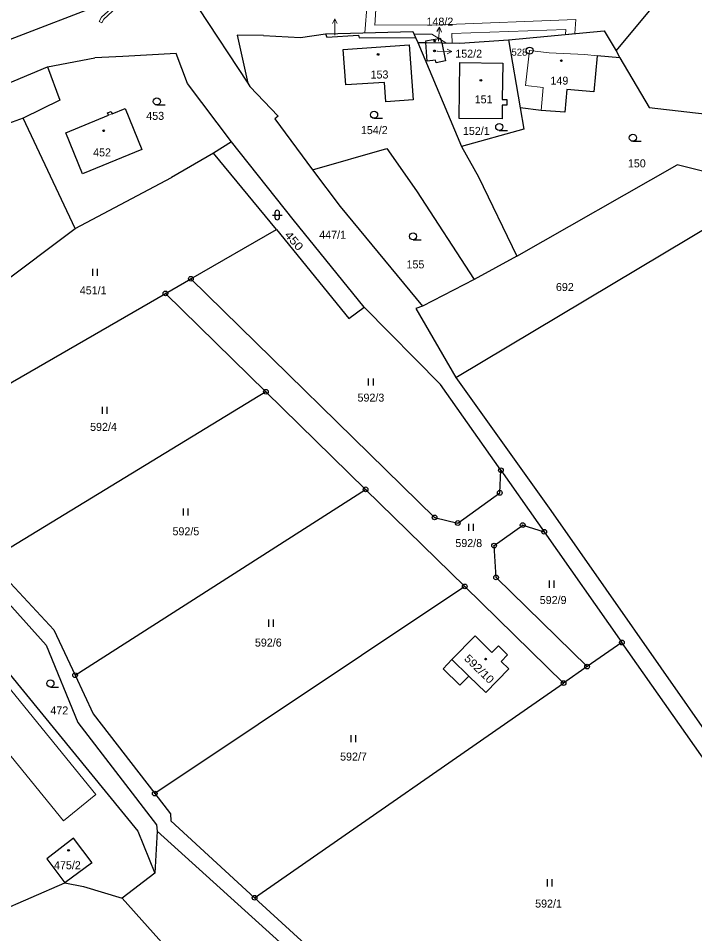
# Model space of a CAD drawing. Extents: x -727701 to -724405, y -960481 to -957284.
# Drawn here: x -726671.5 to -726527.9, y -958402.3 to -958207.9 of the extents above; entities that cross this region are included whole.
import ezdxf
from ezdxf.enums import TextEntityAlignment as Align

# ---------------------------------------------------------------- set-up
doc = ezdxf.new("R2010")
doc.units = 0
doc.header["$LTSCALE"] = 0.68
for name, color, linetype, lineweight in [('1', 7, 'Continuous', 25), ('13', 7, 'Continuous', 13), ('3', 7, 'Continuous', 25), ('4', 7, 'Continuous', 13), ('5', 7, 'Continuous', 25), ('7', 7, 'Continuous', 13), ('8', 7, 'Continuous', 25)]:
    doc.layers.add(name, color=color, linetype=linetype, lineweight=lineweight)
doc.layers.add('2', color=7, linetype='Continuous')

msp = doc.modelspace()

# ---------------------------------------------------------------- linework, layer by layer
at = {"layer": '1'}
for p, q in [((-726698.6, -958222.18), (-726650.53, -958203.52)), ((-726544.56, -958214.79), (-726535.63, -958204.12)), ((-726633.29, -958205.71), (-726622.75, -958221.7)), ((-726606.3, -958211.2), (-726587.7, -958210.7)), ((-726587.7, -958210.7), (-726587.17, -958211.95)), ((-726567.38, -958212.48), (-726547.13, -958210.56)), ((-726547.13, -958210.56), (-726544.56, -958214.79)), ((-726619.45, -958211.55), (-726625, -958211.5)), ((-726625, -958211.5), (-726622.75, -958221.7)), ((-726619.45, -958211.55), (-726611.6, -958211.95)), ((-726611.6, -958211.95), (-726606.3, -958211.2)), ((-726606.3, -958211.2), (-726606.01, -958211.92)), ((-726606.01, -958211.92), (-726599.29, -958211.45)), ((-726599.29, -958211.45), (-726599.13, -958212.08)), ((-726599.13, -958212.08), (-726587.17, -958211.95)), ((-726587.17, -958211.95), (-726586.7, -958213.05)), ((-726581.77, -958212.22), (-726585.02, -958212.76)), ((-726585.02, -958212.76), (-726584.99, -958213.07)), ((-726581.58, -958213.12), (-726581.77, -958212.22)), ((-726567.38, -958212.48), (-726564.95, -958226.93)), ((-726602.5, -958214.5), (-726588.5, -958213.5)), ((-726601.96, -958222.05), (-726602.5, -958214.5)), ((-726588.5, -958213.5), (-726587.66, -958225.23)), ((-726586.7, -958213.05), (-726584.99, -958213.07)), ((-726586.7, -958213.05), (-726577.38, -958235.15)), ((-726584.65, -958217), (-726584.99, -958213.07)), ((-726584.99, -958213.07), (-726581.58, -958213.12)), ((-726581.58, -958213.12), (-726580.81, -958216.9)), ((-726544.56, -958214.79), (-726543.75, -958216.31)), ((-726665.3, -958218.22), (-726655.26, -958216.27)), ((-726649.33, -958216.03), (-726655.26, -958216.27)), ((-726638.02, -958215.37), (-726649.33, -958216.03)), ((-726635.61, -958221.73), (-726638.02, -958215.37)), ((-726548.59, -958215.86), (-726549.31, -958223.52)), ((-726543.75, -958216.31), (-726548.59, -958215.86)), ((-726543.75, -958216.31), (-726537.55, -958226.85)), ((-726682.22, -958225.29), (-726665.3, -958218.22)), ((-726665.3, -958218.22), (-726662.67, -958225.3)), ((-726582.89, -958216.81), (-726584.65, -958217)), ((-726582.78, -958217.33), (-726582.89, -958216.81)), ((-726580.81, -958216.9), (-726582.78, -958217.33)), ((-726577.77, -958217.31), (-726568.63, -958217.42)), ((-726568.63, -958217.42), (-726568.73, -958225.13)), ((-726626.23, -958234.1), (-726635.61, -958221.73)), ((-726622.75, -958221.7), (-726622.35, -958222.4)), ((-726622.35, -958222.4), (-726616.35, -958228.71)), ((-726593.75, -958221.5), (-726601.96, -958222.05)), ((-726593.45, -958225.65), (-726593.75, -958221.5)), ((-726554.99, -958222.99), (-726555.44, -958227.83)), ((-726549.31, -958223.52), (-726554.99, -958222.99)), ((-726662.67, -958225.3), (-726670.49, -958229.12)), ((-726587.66, -958225.23), (-726593.45, -958225.65)), ((-726568.74, -958226.33), (-726568.78, -958229.28)), ((-726567.8, -958226.34), (-726568.74, -958226.33)), ((-726568.73, -958225.13), (-726567.78, -958225.15)), ((-726567.78, -958225.15), (-726567.8, -958226.34)), ((-726652.59, -958228), (-726651.78, -958227.67)), ((-726652.39, -958228.5), (-726652.59, -958228)), ((-726651.78, -958227.67), (-726651.58, -958228.17)), ((-726651.58, -958228.17), (-726648.85, -958227.05)), ((-726648.85, -958227.05), (-726645.28, -958235.78)), ((-726564.95, -958226.93), (-726564.19, -958231.42)), ((-726560.5, -958227.45), (-726564.95, -958226.93)), ((-726555.44, -958227.83), (-726560.5, -958227.45)), ((-726537.55, -958226.85), (-726496.15, -958231.66)), ((-726670.49, -958229.12), (-726679.19, -958232.29)), ((-726659.41, -958252.56), (-726670.49, -958229.12)), ((-726661.44, -958232.2), (-726652.39, -958228.5)), ((-726616.35, -958228.71), (-726617.06, -958229.24)), ((-726617.06, -958229.24), (-726609.02, -958240.05)), ((-726657.87, -958240.93), (-726661.44, -958232.2)), ((-726564.19, -958231.42), (-726577.38, -958235.15)), ((-726626.23, -958234.1), (-726630.03, -958236.53)), ((-726613.14, -958250.6), (-726626.23, -958234.1)), ((-726645.28, -958235.78), (-726657.87, -958240.93)), ((-726609.02, -958240.05), (-726593.25, -958235.58)), ((-726593.25, -958235.58), (-726586.97, -958244.51)), ((-726577.38, -958235.15), (-726573.79, -958241.59)), ((-726630.03, -958236.53), (-726638.99, -958241.7)), ((-726616.69, -958252.72), (-726630.03, -958236.53)), ((-726609.02, -958240.05), (-726603.19, -958247.88)), ((-726565.62, -958258.38), (-726531.6, -958239.03)), ((-726511.47, -958244.03), (-726531.6, -958239.03)), ((-726659.41, -958252.56), (-726638.99, -958241.7)), ((-726573.79, -958241.59), (-726565.62, -958258.38)), ((-726586.97, -958244.51), (-726574.72, -958263.36)), ((-726578.57, -958284.19), (-726511.47, -958244.03)), ((-726603.19, -958247.88), (-726585.67, -958269.02)), ((-726598.06, -958269.21), (-726613.14, -958250.6)), ((-726680.8, -958268.5), (-726659.41, -958252.56)), ((-726634.86, -958263.21), (-726616.69, -958252.72)), ((-726565.62, -958258.38), (-726574.72, -958263.36)), ((-726640.26, -958266.33), (-726634.86, -958263.21)), ((-726634.86, -958263.21), (-726583.1, -958313.87)), ((-726574.72, -958263.36), (-726585.67, -958269.02)), ((-726686.53, -958293.04), (-726640.26, -958266.33)), ((-726618.94, -958287.19), (-726640.26, -958266.33)), ((-726598.06, -958269.21), (-726581.84, -958285.64)), ((-726585.67, -958269.02), (-726587.11, -958269.5)), ((-726587.11, -958269.5), (-726578.57, -958284.19)), ((-726578.57, -958284.19), (-726558.45, -958312.44)), ((-726569.01, -958303.87), (-726581.84, -958285.64)), ((-726618.94, -958287.19), (-726677.69, -958323.03)), ((-726597.76, -958307.92), (-726618.94, -958287.19)), ((-726569.26, -958308.66), (-726569.01, -958303.87)), ((-726569.01, -958303.87), (-726561.17, -958315.01)), ((-726659.45, -958347.38), (-726597.76, -958307.92)), ((-726576.7, -958328.53), (-726597.76, -958307.92)), ((-726578.18, -958315.07), (-726569.26, -958308.66)), ((-726583.1, -958313.87), (-726578.18, -958315.07)), ((-726558.45, -958312.44), (-726504.95, -958388.96)), ((-726570.47, -958319.87), (-726564.4, -958315.51)), ((-726564.4, -958315.51), (-726559.83, -958316.93)), ((-726687.74, -958316.39), (-726665.6, -958341)), ((-726570.06, -958326.63), (-726570.47, -958319.87)), ((-726677.69, -958323.03), (-726664, -958337.75)), ((-726550.71, -958345.56), (-726570.06, -958326.63)), ((-726576.7, -958328.53), (-726642.52, -958372.51)), ((-726555.73, -958349.05), (-726576.7, -958328.53)), ((-726664, -958337.75), (-726659.45, -958347.38)), ((-726579.41, -958344.07), (-726574.49, -958339.03)), ((-726574.49, -958339.03), (-726570.93, -958342.53)), ((-726665.6, -958341), (-726658.89, -958357.45)), ((-726570.93, -958342.53), (-726569.55, -958341.13)), ((-726569.55, -958341.13), (-726567.59, -958343.03)), ((-726543.34, -958340.44), (-726550.71, -958345.56)), ((-726507.9, -958390.97), (-726543.34, -958340.44)), ((-726567.59, -958343.03), (-726568.98, -958344.44)), ((-726581.31, -958346.01), (-726579.41, -958344.07)), ((-726568.98, -958344.44), (-726567.34, -958346.06)), ((-726577.77, -958349.53), (-726581.31, -958346.01)), ((-726567.34, -958346.06), (-726572.24, -958351.09)), ((-726550.71, -958345.56), (-726555.73, -958349.05)), ((-726673.24, -958347.31), (-726646.16, -958380.52)), ((-726659.45, -958347.38), (-726655.58, -958355.57)), ((-726575.83, -958347.57), (-726577.77, -958349.53)), ((-726572.24, -958351.09), (-726575.83, -958347.57)), ((-726621.33, -958394.65), (-726555.73, -958349.05)), ((-726655.58, -958355.57), (-726642.52, -958372.51)), ((-726658.89, -958357.45), (-726642.18, -958379.16)), ((-726642.52, -958372.51), (-726639.18, -958376.84)), ((-726639.18, -958376.84), (-726639.14, -958378.33)), ((-726642.18, -958379.16), (-726642.02, -958380.5)), ((-726639.14, -958378.33), (-726621.33, -958394.65)), ((-726646.16, -958380.52), (-726642.53, -958389.45)), ((-726642.02, -958380.5), (-726642.53, -958389.45)), ((-726642.02, -958380.5), (-726601.94, -958416.75)), ((-726659.77, -958382), (-726665.45, -958386.4)), ((-726655.85, -958387.19), (-726659.77, -958382)), ((-726665.45, -958386.4), (-726661.65, -958391.45)), ((-726656, -958387.3), (-726661.65, -958391.45)), ((-726656, -958387.3), (-726655.85, -958387.19)), ((-726642.53, -958389.45), (-726649.48, -958394.74)), ((-726678.65, -958398.83), (-726661.65, -958391.45)), ((-726661.65, -958391.45), (-726657.65, -958392.22)), ((-726657.65, -958392.22), (-726649.48, -958394.74)), ((-726649.48, -958394.74), (-726627.27, -958419.4)), ((-726621.33, -958394.65), (-726599.31, -958414.82))]:
    msp.add_line(p, q, dxfattribs=at)
for points in [[(-726581.58, -958213.12), (-726577.72, -958213.17), (-726567.38, -958212.48)], [(-726568.78, -958229.28), (-726577.92, -958229.16), (-726577.77, -958217.31)], [(-726616.69, -958252.72), (-726601.3, -958271.65), (-726598.06, -958269.21)], [(-726561.17, -958315.01), (-726559.83, -958316.93), (-726543.34, -958340.44)]]:
    msp.add_lwpolyline(points, dxfattribs=at)
at = {"layer": '13'}
for points in [[(-726683.98, -958176.09), (-726684.86, -958176.33), (-726686.62, -958180.59), (-726678.19, -958185.71), (-726669.71, -958191.56), (-726652.85, -958201.35), (-726649.93, -958203.4), (-726651.14, -958205.22), (-726653.81, -958207.69), (-726654.31, -958208.57), (-726653.79, -958208.86), (-726653.33, -958208.07), (-726650.68, -958205.62), (-726649.1, -958203.24), (-726652.53, -958200.84), (-726669.38, -958191.05), (-726677.87, -958185.21), (-726685.87, -958180.34), (-726684.42, -958176.83), (-726683.29, -958176.52)], [(-726594.48, -958204.65), (-726597.46, -958204.73), (-726597.89, -958210.97), (-726587.7, -958210.7), (-726587.45, -958211.3), (-726583.72, -958211.27), (-726580.73, -958213.13), (-726579.4, -958213.15), (-726579.42, -958211.16), (-726555.25, -958210.25), (-726555.32, -958211.34), (-726553.3, -958211.15), (-726553.11, -958208.16), (-726582.05, -958209.26), (-726595.78, -958209.36), (-726595.55, -958206.05), (-726588.27, -958204.55)]]:
    msp.add_lwpolyline(points, close=True, dxfattribs=at)
at = {"layer": '3'}
for p, q in [((-726642.093, -958226.3), (-726640.343, -958226.3)), ((-726595.953, -958229.14), (-726594.203, -958229.14)), ((-726569.383, -958231.72), (-726567.633, -958231.72)), ((-726541.003, -958234.02), (-726539.253, -958234.02)), ((-726617.511, -958249.671), (-726615.509, -958249.671)), ((-726617.011, -958249.171), (-726617.011, -958250.172)), ((-726616.009, -958250.172), (-726616.009, -958249.171)), ((-726587.683, -958254.94), (-726585.933, -958254.94)), ((-726655.701, -958262.6), (-726655.701, -958261.1)), ((-726654.7, -958262.6), (-726654.7, -958261.1)), ((-726597.111, -958285.9), (-726597.111, -958284.4)), ((-726596.11, -958285.9), (-726596.11, -958284.4)), ((-726653.641, -958291.87), (-726653.641, -958290.37)), ((-726652.64, -958291.87), (-726652.64, -958290.37)), ((-726636.431, -958313.46), (-726636.431, -958311.96)), ((-726635.43, -958313.46), (-726635.43, -958311.96)), ((-726575.811, -958316.73), (-726575.811, -958315.23)), ((-726574.81, -958316.73), (-726574.81, -958315.23)), ((-726558.711, -958328.8), (-726558.711, -958327.3)), ((-726557.71, -958328.8), (-726557.71, -958327.3)), ((-726618.341, -958337.08), (-726618.341, -958335.58)), ((-726617.34, -958337.08), (-726617.34, -958335.58)), ((-726664.693, -958349.89), (-726662.943, -958349.89)), ((-726600.841, -958361.59), (-726600.841, -958360.09)), ((-726599.84, -958361.59), (-726599.84, -958360.09)), ((-726559.121, -958392.22), (-726559.121, -958390.72)), ((-726558.12, -958392.22), (-726558.12, -958390.72))]:
    msp.add_line(p, q, dxfattribs=at)
for centre in [(-726642.0929, -958225.5498), (-726595.9529, -958228.3898), (-726569.3829, -958230.9698), (-726541.0029, -958233.2698), (-726587.6829, -958254.1898), (-726664.6929, -958349.1398)]:
    msp.add_circle(centre, 0.75, dxfattribs=at)
for centre, start, end in [((-726616.51, -958249.1709), 0, 180), ((-726616.51, -958250.1709), 180, 359.98789)]:
    msp.add_arc(centre, 0.5, start, end, dxfattribs=at)
at = {"layer": '4'}
for p, q in [((-726563.77, -958222.16), (-726562.93, -958214.76)), ((-726562.93, -958214.76), (-726558.76, -958215.25)), ((-726558.76, -958215.25), (-726551.21, -958215.61)), ((-726551.21, -958215.61), (-726548.59, -958215.86)), ((-726560.05, -958222.6), (-726563.77, -958222.16)), ((-726560.5, -958227.45), (-726560.05, -958222.6)), ((-726652.39, -958228.5), (-726651.58, -958228.17)), ((-726579.41, -958344.07), (-726575.83, -958347.57)), ((-726674.73, -958348.52), (-726655.02, -958372.69)), ((-726661.93, -958378.32), (-726676.84, -958360.02)), ((-726655.02, -958372.69), (-726661.93, -958378.32))]:
    msp.add_line(p, q, dxfattribs=at)
at = {"layer": '5'}
for centre in [(-726583.0868, -958212.7092), (-726583.1368, -958214.8192), (-726595.1068, -958215.5792), (-726556.1868, -958216.8992), (-726573.2768, -958221.0892), (-726653.3668, -958231.7892), (-726572.2768, -958343.9692), (-726660.8368, -958384.5792)]:
    msp.add_circle(centre, 0.175, dxfattribs=at)
at = {"layer": '7'}
for p, q in [((-726604.258, -958207.999), (-726604.776, -958208.992)), ((-726582.048, -958209.77), (-726582.635, -958210.724)), ((-726579.459, -958214.942), (-726580.452, -958214.424))]:
    msp.add_line(p, q, dxfattribs=at)
for points in [[(-726604.32, -958211.47), (-726604.31, -958211), (-726604.258, -958207.999), (-726603.774, -958209.01)], [(-726582.31, -958212.76), (-726582.048, -958209.77), (-726581.637, -958210.812)], [(-726582.6, -958214.89), (-726582.46, -958214.89), (-726579.459, -958214.942), (-726580.47, -958215.426)]]:
    msp.add_lwpolyline(points, dxfattribs=at)
at = {"layer": '8'}
for centre, radius in [((-726562.93, -958214.7598), 0.75), ((-726562.93, -958214.7598), 0.03), ((-726634.86, -958263.2099), 0.5), ((-726634.86, -958263.2099), 0.0303), ((-726640.26, -958266.3299), 0.5), ((-726640.26, -958266.3299), 0.0303), ((-726618.94, -958287.1899), 0.5), ((-726618.94, -958287.1899), 0.0303), ((-726569.01, -958303.8699), 0.5), ((-726569.01, -958303.8699), 0.0303), ((-726597.76, -958307.9199), 0.5), ((-726597.76, -958307.9199), 0.0303), ((-726569.26, -958308.6599), 0.5), ((-726569.26, -958308.6599), 0.0303), ((-726583.1, -958313.8699), 0.5), ((-726583.1, -958313.8699), 0.0303), ((-726578.18, -958315.0699), 0.5), ((-726578.18, -958315.0699), 0.0303), ((-726564.4, -958315.5099), 0.5), ((-726564.4, -958315.5099), 0.0303), ((-726559.83, -958316.9299), 0.5), ((-726559.83, -958316.9299), 0.0303), ((-726570.47, -958319.8699), 0.5), ((-726570.47, -958319.8699), 0.0303), ((-726570.06, -958326.6299), 0.5), ((-726570.06, -958326.6299), 0.0303), ((-726576.7, -958328.5299), 0.5), ((-726576.7, -958328.5299), 0.0303), ((-726543.34, -958340.4399), 0.5), ((-726543.34, -958340.4399), 0.0303), ((-726659.45, -958347.3799), 0.5), ((-726550.71, -958345.5599), 0.5), ((-726550.71, -958345.5599), 0.0303), ((-726659.45, -958347.3799), 0.0303), ((-726555.73, -958349.0499), 0.5), ((-726555.73, -958349.0499), 0.0303), ((-726642.52, -958372.5099), 0.5), ((-726642.52, -958372.5099), 0.0303), ((-726621.33, -958394.6499), 0.5), ((-726621.33, -958394.6499), 0.0303)]:
    msp.add_circle(centre, radius, dxfattribs=at)

# ---------------------------------------------------------------- texts
at = {"layer": '2'}
for s, p in [('148/2', (-726581.98, -958209.455)), ('152/1', (-726574.25, -958232.665)), ('447/1', (-726604.76, -958254.715)), ('451/1', (-726655.61, -958266.515)), ('592/3', (-726596.63, -958289.295)), ('592/4', (-726653.42, -958295.505)), ('592/5', (-726635.92, -958317.675)), ('592/8', (-726575.85, -958320.175)), ('592/9', (-726557.93, -958332.275)), ('592/6', (-726618.42, -958341.305)), ('592/7', (-726600.33, -958365.515)), ('592/1', (-726558.91, -958396.725))]:
    msp.add_text(s, height=1.7, dxfattribs=at).set_placement(p, align=Align.CENTER)
for s, p in [('152/2', (-726578.71, -958216.262)), ('153', (-726596.71, -958220.685)), ('149', (-726558.5, -958221.985)), ('151', (-726574.59, -958225.955)), ('453', (-726644.34, -958229.465)), ('154/2', (-726598.76, -958232.485)), ('452', (-726655.62, -958237.225)), ('150', (-726542.06, -958239.555)), ('155', (-726589.07, -958261.005)), ('692', (-726557.34, -958265.805)), ('472', (-726664.7, -958355.715)), ('475/2', (-726663.93, -958388.585))]:
    msp.add_text(s, height=1.7, dxfattribs=at).set_placement(p)
at = {"layer": '2', "width": 1.2}
msp.add_text('450', height=1.7, rotation=311, dxfattribs=at).set_placement((-726615.09, -958253.988))
at = {"layer": '2', "width": 1.1}
msp.add_text('592/10', height=1.7, rotation=316, dxfattribs=at).set_placement((-726574.214, -958346.6652), align=Align.CENTER)
at = {"layer": '8'}
msp.add_text('528', height=1.5, dxfattribs=at).set_placement((-726566.77, -958215.835))

doc.saveas('drawing.dxf')
